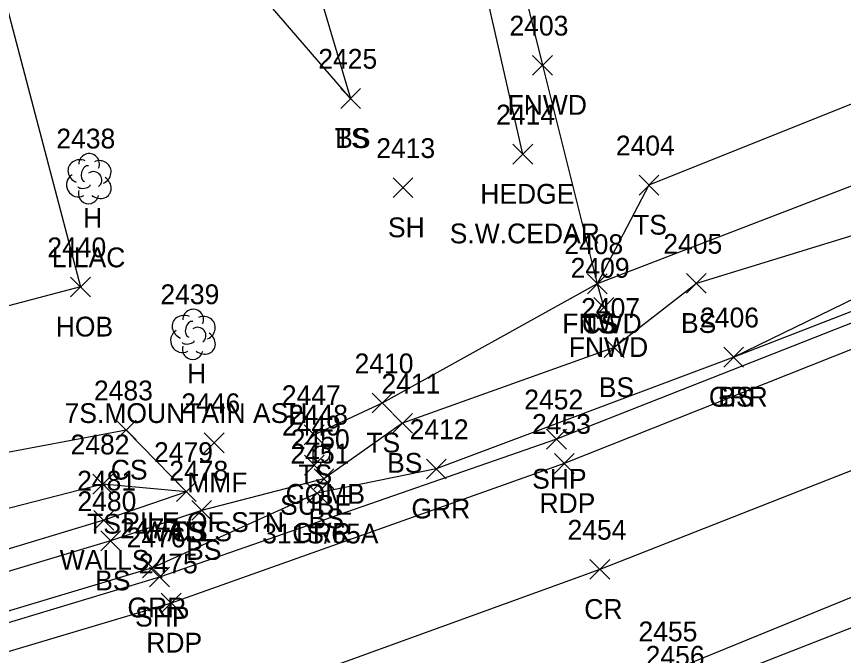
# Model space of a CAD drawing. Extents: x 1520648 to 1523413, y 732854 to 735518.
# Drawn here: x 1521837.4 to 1521920.9, y 733711.6 to 733776.2 of the extents above; entities that cross this region are included whole.
import ezdxf

# ---------------------------------------------------------------- set-up
doc = ezdxf.new("R2010")
doc.units = 0
for name, color, linetype in [('L_A', 7, 'Continuous'), ('L_C', 7, 'Continuous'), ('L_I', 7, 'Continuous'), ('L_TIC', 7, 'Continuous'), ('LAHR', 7, 'Continuous'), ('LBC', 7, 'Continuous'), ('LELB', 7, 'Continuous'), ('LFNC', 7, 'Continuous'), ('LTD', 7, 'Continuous'), ('LWS', 7, 'Continuous'), ('P_A', 7, 'Continuous'), ('P_I', 7, 'Continuous'), ('P_TIC', 7, 'Continuous'), ('PET', 7, 'Continuous'), ('PRC', 7, 'Continuous'), ('PSP', 7, 'Continuous'), ('R_A', 7, 'Continuous'), ('R_I', 7, 'Continuous'), ('R_TIC', 7, 'Continuous'), ('RGR', 7, 'Continuous'), ('U_A', 7, 'Continuous'), ('U_C', 7, 'Continuous'), ('U_I', 7, 'Continuous'), ('U_TIC', 7, 'Continuous'), ('UP', 7, 'Continuous')]:
    doc.layers.add(name, color=color, linetype=linetype)

msp = doc.modelspace()

# ---------------------------------------------------------------- linework, layer by layer
at = {"layer": 'L_TIC'}
for points in [[(1521889.545, 733770.234), (1521891.545, 733772.234)], [(1521891.545, 733770.234), (1521889.545, 733772.234)], [(1521870.16, 733766.887), (1521872.16, 733768.887)], [(1521872.16, 733766.887), (1521870.16, 733768.887)], [(1521870.16, 733766.887), (1521872.16, 733768.887)], [(1521872.16, 733766.887), (1521870.16, 733768.887)], [(1521887.55, 733761.255), (1521889.55, 733763.255)], [(1521889.55, 733761.255), (1521887.55, 733763.255)], [(1521900.287, 733758.134), (1521902.287, 733760.134)], [(1521902.287, 733758.134), (1521900.287, 733760.134)], [(1521875.445, 733757.871), (1521877.445, 733759.871)], [(1521877.445, 733757.871), (1521875.445, 733759.871)], [(1521895.074, 733748.167), (1521897.074, 733750.167)], [(1521897.074, 733748.167), (1521895.074, 733750.167)], [(1521895.074, 733748.167), (1521897.074, 733750.167)], [(1521897.074, 733748.167), (1521895.074, 733750.167)], [(1521895.074, 733748.167), (1521897.074, 733750.167)], [(1521897.074, 733748.167), (1521895.074, 733750.167)], [(1521905.082, 733748.21), (1521907.082, 733750.21)], [(1521907.082, 733748.21), (1521905.082, 733750.21)], [(1521842.882, 733747.849), (1521844.882, 733749.849)], [(1521844.882, 733747.849), (1521842.882, 733749.849)], [(1521895.73, 733745.781), (1521897.73, 733747.781)], [(1521897.73, 733745.781), (1521895.73, 733747.781)], [(1521896.782, 733741.726), (1521898.782, 733743.726)], [(1521898.782, 733741.726), (1521896.782, 733743.726)], [(1521908.848, 733740.767), (1521910.848, 733742.767)], [(1521910.848, 733740.767), (1521908.848, 733742.767)], [(1521873.343, 733736.13), (1521875.343, 733738.13)], [(1521875.343, 733736.13), (1521873.343, 733738.13)], [(1521875.406, 733734.089), (1521877.406, 733736.089)], [(1521877.406, 733734.089), (1521875.406, 733736.089)], [(1521847.503, 733733.399), (1521849.503, 733735.399)], [(1521849.503, 733733.399), (1521847.503, 733735.399)], [(1521866.478, 733732.923), (1521868.478, 733734.923)], [(1521868.478, 733732.923), (1521866.478, 733734.923)], [(1521856.379, 733732.106), (1521858.379, 733734.106)], [(1521858.379, 733732.106), (1521856.379, 733734.106)], [(1521867.468, 733728.473), (1521869.468, 733730.473)], [(1521869.468, 733728.473), (1521867.468, 733730.473)], [(1521845.144, 733727.944), (1521847.144, 733729.944)], [(1521847.144, 733727.944), (1521845.144, 733729.944)], [(1521853.58, 733727.173), (1521855.58, 733729.173)], [(1521855.58, 733727.173), (1521853.58, 733729.173)], [(1521853.58, 733727.173), (1521855.58, 733729.173)], [(1521855.58, 733727.173), (1521853.58, 733729.173)], [(1521853.58, 733727.173), (1521855.58, 733729.173)], [(1521855.58, 733727.173), (1521853.58, 733729.173)], [(1521855.113, 733725.295), (1521857.113, 733727.295)], [(1521857.113, 733725.295), (1521855.113, 733727.295)], [(1521845.241, 733724.293), (1521847.241, 733726.293)], [(1521847.241, 733724.293), (1521845.241, 733726.293)], [(1521845.926, 733722.217), (1521847.926, 733724.217)], [(1521847.926, 733722.217), (1521845.926, 733724.217)]]:
    msp.add_lwpolyline(points, dxfattribs=at)
at = {"layer": 'LAHR'}
msp.add_lwpolyline([(1521888.55, 733762.255), (1521883.637, 733783.905), (1521877.571, 733807.43), (1521874.21, 733824.224), (1521892.527, 733853.504)], dxfattribs=at)
at = {"layer": 'LBC'}
msp.add_lwpolyline([(1521835.145, 733782.05), (1521843.882, 733748.849), (1521828.183, 733744.717), (1521821.831, 733742.985), (1521820.48, 733742.721), (1521819.445, 733746.724)], dxfattribs=at)
at = {"layer": 'LELB'}
for points in [[(1522074.665, 733922.228), (1522083.883, 733914.938), (1522085.489, 733904.133), (1522101.868, 733884.89), (1522107.237, 733877.569), (1522111.252, 733871.848), (1522110.649, 733869.41), (1522100.331, 733859.173), (1522100.269, 733856.435), (1522101.54, 733853.052), (1522099.302, 733851.621), (1522097.995, 733854.753), (1522097.241, 733854.62), (1522077.44, 733842.598), (1522038.26, 733821.738), (1522024.978, 733813.097), (1522007.394, 733798.444), (1521977.074, 733777.169), (1521956.259, 733766.141), (1521934.496, 733753.743), (1521909.848, 733741.767)], [(1521935.5, 733911.289), (1521950.9, 733894.839), (1521962.915, 733884.057), (1521979.81, 733864.62), (1521996.139, 733844.795), (1522019.287, 733822.837), (1522000.656, 733804.638), (1521971.808, 733783.007), (1521953.741, 733771.36), (1521896.074, 733749.167)], [(1521912.449, 733877.558), (1521921.717, 733856.63), (1521929.761, 733836.233), (1521943.688, 733808.595), (1521957.263, 733787.466), (1521947.51, 733781.711), (1521925.598, 733768.851), (1521901.287, 733759.134), (1521896.074, 733749.167), (1521874.343, 733737.13), (1521867.478, 733733.923)], [(1521882.775, 733859.993), (1521870.293, 733849.741), (1521862.415, 733830.59), (1521861.758, 733799.522), (1521871.16, 733767.887)], [(1521871.16, 733767.887), (1521855.645, 733785.898), (1521854.205, 733803.93), (1521849.198, 733835.526), (1521844.963, 733858.394)], [(1521953.741, 733771.36), (1521932.171, 733757.205), (1521906.082, 733749.21), (1521897.782, 733742.726), (1521876.406, 733735.089), (1521868.468, 733729.473), (1521856.113, 733726.295), (1521846.926, 733723.217), (1521807.832, 733711.49), (1521796.012, 733708.16), (1521783.934, 733704.847), (1521779.712, 733703.434)], [(1521854.58, 733728.173), (1521848.503, 733734.399), (1521822.728, 733729.558), (1521806.487, 733722.551), (1521806.109, 733715.951)], [(1521854.58, 733728.173), (1521846.144, 733728.944), (1521820.589, 733722.388), (1521806.109, 733715.951), (1521795.324, 733711.839), (1521781.883, 733709.574)]]:
    msp.add_lwpolyline(points, dxfattribs=at)
at = {"layer": 'LFNC'}
msp.add_lwpolyline([(1521935.5, 733911.289), (1521921.213, 733890.001), (1521912.449, 733877.558), (1521901.647, 733861.043), (1521888.577, 733840.724), (1521877.566, 733824.178), (1521883.213, 733800.863), (1521890.545, 733771.234), (1521896.074, 733749.167), (1521896.73, 733746.781)], dxfattribs=at)
at = {"layer": 'LTD'}
for p, q in [((1521844.707, 733759.836), (1521844.707, 733759.836)), ((1521844.707, 733759.836), (1521844.707, 733759.836)), ((1521855.226, 733744.113), (1521855.226, 733744.113)), ((1521855.226, 733744.113), (1521855.226, 733744.113))]:
    msp.add_line(p, q, dxfattribs=at)
for centre in [(1521844.754, 733761.27), (1521855.273, 733745.547)]:
    msp.add_arc(centre, 1.047, 335.52715, 180.95627, dxfattribs=at)
for centre, major_axis, ratio, start_param, end_param in [((1521843.916, 733760.502), (1.21, -0.512), 0.895232, 1.570796, 4.712389), ((1521845.749, 733760.419), (-1.141, -0.483), 0.949671, 1.570796, 4.712389), ((1521844.499, 733760.294), (-0.208, -0.792), 0.645439, 3.141593, 6.283185), ((1521843.624, 733759.127), (0.584, -1.042), 0.959034, 3.141593, 6.283185), ((1521845.207, 733759.669), (-0.5, 0.667), 0.989748, 3.141593, 6.283185), ((1521845.708, 733759.003), (-1.09, 0.792), 0.841452, 1.570796, 4.712389), ((1521844.708, 733758.336), (0.265, 1.061), 0.942809, 1.570796, 4.712389), ((1521844.249, 733759.086), (-0.625, -0.083), 0.423636, 0, 3.141593), ((1521854.434, 733744.78), (1.21, -0.512), 0.895232, 1.570796, 4.712389), ((1521856.268, 733744.697), (-1.141, -0.483), 0.949671, 1.570796, 4.712389), ((1521855.018, 733744.572), (-0.208, -0.792), 0.645439, 3.141593, 6.283185), ((1521854.143, 733743.405), (0.584, -1.042), 0.959034, 3.141593, 6.283185), ((1521855.726, 733743.947), (-0.5, 0.667), 0.989748, 3.141593, 6.283185), ((1521854.768, 733743.363), (-0.625, -0.083), 0.423636, 0, 3.141593), ((1521856.226, 733743.28), (-1.09, 0.792), 0.841452, 1.570796, 4.712389), ((1521855.226, 733742.613), (0.265, 1.061), 0.942809, 1.570796, 4.712389)]:
    msp.add_ellipse(centre, major_axis=major_axis, ratio=ratio, start_param=start_param, end_param=end_param, dxfattribs=at)
at = {"layer": 'LWS'}
msp.add_lwpolyline([(1521854.58, 733728.173), (1521846.241, 733725.293), (1521807.401, 733713.558)], dxfattribs=at)
at = {"layer": 'P_TIC'}
for points in [[(1521890.961, 733732.483), (1521892.961, 733734.483)], [(1521892.961, 733732.483), (1521890.961, 733734.483)], [(1521891.742, 733730.021), (1521893.742, 733732.021)], [(1521893.742, 733730.021), (1521891.742, 733732.021)], [(1521895.324, 733719.332), (1521897.324, 733721.332)], [(1521897.324, 733719.332), (1521895.324, 733721.332)], [(1521850.863, 733718.561), (1521852.863, 733720.561)], [(1521852.863, 733718.561), (1521850.863, 733720.561)], [(1521852.037, 733715.934), (1521854.037, 733717.934)], [(1521854.037, 733715.934), (1521852.037, 733717.934)]]:
    msp.add_lwpolyline(points, dxfattribs=at)
at = {"layer": 'PET'}
for points in [[(1522409.889, 734185.458), (1522384.803, 734151.862), (1522362.154, 734120.963), (1522340.089, 734090.379), (1522317.27, 734060.024), (1522297.221, 734033.868), (1522262.688, 733990.171), (1522247.435, 733972.23), (1522223.908, 733946.238), (1522192.475, 733913.956), (1522164.522, 733888.054), (1522124.702, 733855.724), (1522089.977, 733831.334), (1522050.332, 733806.095), (1522008.227, 733782.155), (1521961.733, 733759.371), (1521937.846, 733748.917), (1521892.742, 733731.021), (1521853.037, 733716.934), (1521810.117, 733704.128), (1521784.901, 733696.796), (1521738.039, 733684.332), (1521683.498, 733669.737)], [(1522293.194, 733992.175), (1522263.712, 733955.946), (1522232.455, 733921.589), (1522205.93, 733894.992), (1522171.676, 733864.451), (1522150.755, 733846.951), (1522111.89, 733818.73), (1522077.257, 733795.558), (1522046.35, 733777.345), (1522014.71, 733760.043), (1521992.386, 733748.515), (1521963.746, 733735.045), (1521947.246, 733727.941), (1521903.494, 733710.068), (1521845.394, 733690.649), (1521824.845, 733681.254), (1521803.807, 733674.865), (1521790.983, 733674.845), (1521764.049, 733667.923), (1521729.464, 733658.425), (1521691.158, 733648.143)]]:
    msp.add_lwpolyline(points, dxfattribs=at)
at = {"layer": 'PRC'}
msp.add_lwpolyline([(1522254.708, 733962.62), (1522224.204, 733928.998), (1522197.911, 733902.998), (1522164.255, 733873.016), (1522142.54, 733855.168), (1522104.412, 733827.43), (1522070.845, 733804.697), (1522039.569, 733786.252), (1522009.598, 733770.035), (1521986.99, 733758.562), (1521958.12, 733745.427), (1521942.227, 733738.37), (1521896.324, 733720.332), (1521857.71, 733706.322), (1521841.616, 733701.433), (1521812.172, 733692.842), (1521787.027, 733685.658), (1521768.249, 733680.623), (1521726.089, 733669.372), (1521688.171, 733658.559)], dxfattribs=at)
at = {"layer": 'PSP'}
for points in [[(1522407.438, 734186.957), (1522382.703, 734153.399), (1522359.979, 734122.447), (1522337.917, 734092.022), (1522315.008, 734061.409), (1522295.214, 734035.758), (1522260.619, 733991.788), (1522245.877, 733973.988), (1522222.051, 733948.064), (1522190.446, 733915.418), (1522160.989, 733888.489), (1522154.255, 733883.337), (1522127.344, 733861.553), (1522088.304, 733833.578), (1522048.983, 733808.783), (1522007.27, 733785.063), (1521960.899, 733762.469), (1521936.677, 733751.076), (1521891.961, 733733.483), (1521851.863, 733719.561), (1521809.017, 733706.622), (1521784.101, 733699.987), (1521736.058, 733688.523), (1521682.585, 733672.906)], [(1522408.205, 734139.279), (1522381.044, 734102.475), (1522353.021, 734064.874), (1522324.006, 734025.281), (1522296.174, 733989.549), (1522266.628, 733953.31), (1522235.292, 733918.787), (1522209.781, 733890.984), (1522201.901, 733884.12), (1522173.488, 733859.111), (1522154.026, 733843.415), (1522113.548, 733816.073), (1522079.344, 733793.188), (1522048.296, 733774.459), (1522016.588, 733757.423), (1521993.944, 733745.829), (1521965.161, 733732.44), (1521948.662, 733724.972), (1521904.277, 733707.61), (1521888.633, 733701.989), (1521847.287, 733686.723), (1521809.288, 733673.666)]]:
    msp.add_lwpolyline(points, dxfattribs=at)
at = {"layer": 'R_TIC'}
for points in [[(1521908.848, 733740.767), (1521910.848, 733742.767)], [(1521910.848, 733740.767), (1521908.848, 733742.767)], [(1521878.817, 733729.479), (1521880.817, 733731.479)], [(1521880.817, 733729.479), (1521878.817, 733731.479)], [(1521866.784, 733727.022), (1521868.784, 733729.022)], [(1521868.784, 733727.022), (1521866.784, 733729.022)], [(1521850.141, 733719.486), (1521852.141, 733721.486)], [(1521852.141, 733719.486), (1521850.141, 733721.486)]]:
    msp.add_lwpolyline(points, dxfattribs=at)
at = {"layer": 'RGR'}
msp.add_lwpolyline([(1522126.874, 733869.88), (1522125.456, 733863.286), (1522121.4, 733858.507), (1522087.424, 733834.282), (1522048.407, 733809.657), (1522007.43, 733786.325), (1521960.484, 733763.268), (1521936.152, 733751.967), (1521909.848, 733741.767), (1521879.817, 733730.479), (1521867.784, 733728.022), (1521851.141, 733720.486), (1521809.104, 733707.865), (1521796.227, 733704.909), (1521783.934, 733704.847)], dxfattribs=at)
at = {"layer": 'U_TIC'}
for points in [[(1521866.503, 733729.851), (1521868.503, 733731.851)], [(1521868.503, 733729.851), (1521866.503, 733731.851)]]:
    msp.add_lwpolyline(points, dxfattribs=at)
at = {"layer": 'UP'}
for p, q in [((1521868.456, 733733.621), (1521868.206, 733732.787)), ((1521867.373, 733731.121), (1521867.373, 733732.787)), ((1521867.373, 733732.787), (1521869.04, 733732.787)), ((1521869.04, 733732.787), (1521869.04, 733731.121)), ((1521868.206, 733731.954), (1521868.206, 733731.954)), ((1521869.04, 733731.121), (1521867.373, 733731.121)), ((1521867.956, 733730.287), (1521868.206, 733731.121))]:
    msp.add_line(p, q, dxfattribs=at)
msp.add_circle((1521868.206, 733731.954), 0.833, dxfattribs=at)

# ---------------------------------------------------------------- texts
at = {"layer": 'L_A'}
for s, p in [('FNWD', (1521887.009, 733766.234)), ('TS', (1521869.57, 733762.887)), ('BS', (1521869.601, 733762.887)), ('HEDGE', (1521884.25, 733757.255)), ('H', (1521844.14, 733754.836)), ('TS', (1521899.697, 733754.134)), ('SH', (1521874.933, 733753.871)), ('FNWD', (1521892.539, 733744.167)), ('TS', (1521894.484, 733744.167)), ('CS', (1521894.515, 733744.167)), ('BS', (1521904.523, 733744.21)), ('HOB', (1521841.386, 733743.849)), ('FNWD', (1521893.195, 733741.781)), ('H', (1521854.659, 733739.113)), ('BS', (1521896.223, 733737.726)), ('BS', (1521908.289, 733736.767)), ('TS', (1521872.753, 733732.13)), ('BS', (1521874.847, 733730.089)), ('CS', (1521846.944, 733729.399)), ('TS', (1521865.888, 733728.923)), ('MMF', (1521854.662, 733728.106)), ('TS', (1521844.554, 733723.944)), ('BS', (1521866.909, 733724.473)), ('WALLS', (1521850.123, 733723.173)), ('TS', (1521852.989, 733723.173)), ('CS', (1521853.021, 733723.173)), ('BS', (1521854.554, 733721.295)), ('WALLS', (1521841.784, 733720.293)), ('BS', (1521845.367, 733718.217))]:
    msp.add_text(s, height=2, dxfattribs=at).set_placement(p)
at = {"layer": 'L_C'}
for s, p in [('S.W.CEDAR', (1521881.172, 733753.255)), ('LILAC', (1521840.983, 733750.836)), ('7S.MOUNTAIN ASH', (1521842.281, 733735.113)), ('PILE OF STN', (1521848.095, 733724.106))]:
    msp.add_text(s, height=2, dxfattribs=at).set_placement(p)
at = {"layer": 'L_I'}
for s, p in [('2403', (1521887.206, 733774.234)), ('2425', (1521867.9, 733770.887)), ('2425', (1521867.9, 733770.887)), ('2414', (1521885.857, 733765.255)), ('2438', (1521841.448, 733762.836)), ('2413', (1521873.752, 733761.871)), ('2404', (1521897.949, 733762.134)), ('2440', (1521840.536, 733751.849)), ('2408', (1521892.736, 733752.167)), ('2408', (1521892.736, 733752.167)), ('2408', (1521892.736, 733752.167)), ('2405', (1521902.743, 733752.21)), ('2409', (1521893.384, 733749.781)), ('2439', (1521851.958, 733747.113)), ('2407', (1521894.443, 733745.726)), ('2406', (1521906.455, 733744.767)), ('2410', (1521871.564, 733740.13)), ('2411', (1521874.28, 733738.089)), ('2483', (1521845.243, 733737.399)), ('2447', (1521864.218, 733736.923)), ('2446', (1521854.064, 733736.106)), ('2450', (1521865.121, 733732.473)), ('2482', (1521842.885, 733731.944)), ('2479', (1521851.312, 733731.173)), ('2479', (1521851.312, 733731.173)), ('2479', (1521851.312, 733731.173)), ('2478', (1521852.854, 733729.295)), ('2481', (1521843.548, 733728.293)), ('2480', (1521843.58, 733726.217))]:
    msp.add_text(s, height=2, dxfattribs=at).set_placement(p)
at = {"layer": 'P_A'}
for s, p in [('SHP', (1521889.496, 733728.483)), ('RDP', (1521890.231, 733726.021)), ('CR', (1521894.757, 733715.332)), ('SHP', (1521849.398, 733714.561)), ('RDP', (1521850.525, 733711.934))]:
    msp.add_text(s, height=2, dxfattribs=at).set_placement(p)
at = {"layer": 'P_I'}
for s, p in [('2452', (1521888.701, 733736.483)), ('2453', (1521889.483, 733734.021)), ('2454', (1521893.064, 733723.332)), ('2476', (1521848.548, 733722.561)), ('2475', (1521849.777, 733719.934)), ('2455', (1521900.234, 733713.068)), ('2455', (1521900.234, 733713.068)), ('2456', (1521900.962, 733710.61))]:
    msp.add_text(s, height=2, dxfattribs=at).set_placement(p)
at = {"layer": 'R_A'}
for p in [(1521907.337, 733736.767), (1521877.305, 733725.479), (1521865.272, 733723.022), (1521848.629, 733715.486)]:
    msp.add_text('GRR', height=2, dxfattribs=at).set_placement(p)
at = {"layer": 'R_I'}
for s, p in [('2406', (1521906.455, 733744.767)), ('2412', (1521877.124, 733733.479)), ('2451', (1521865.091, 733731.022)), ('2477', (1521847.881, 733723.486))]:
    msp.add_text(s, height=2, dxfattribs=at).set_placement(p)
at = {"layer": 'U_A'}
for s, p in [('COMB', (1521864.592, 733726.954)), ('SUBE', (1521864.038, 733725.851))]:
    msp.add_text(s, height=2, dxfattribs=at).set_placement(p)
at = {"layer": 'U_C'}
msp.add_text('311S/65A', height=2, dxfattribs=at).set_placement((1521862.23, 733722.954))
at = {"layer": 'U_I'}
for s, p in [('2448', (1521864.947, 733734.954)), ('2449', (1521864.235, 733733.851))]:
    msp.add_text(s, height=2, dxfattribs=at).set_placement(p)

doc.saveas('drawing.dxf')
